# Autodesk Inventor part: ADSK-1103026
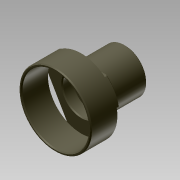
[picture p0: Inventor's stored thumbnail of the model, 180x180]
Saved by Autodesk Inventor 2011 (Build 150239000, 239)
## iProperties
Shininess: 41.0
Length Units: 11272
Angle Units: 11279
Time Units: 11290
Mass Units: 11286
Length Display Precision: 4
Angle Display Precision: 2
Compacted: True
Created: 2000-08
Part Number: ADSK-1103026
Document SubType Name: Modeling
Description: 24 TOOTH CLUTCH GEAR
Mass: 3.13134 g
Surface Area: 23.3651 cm^2
Volume: 1.15548 cm^3
Density: 2.71 g/cm^3
Material: Aluminum-6061
Density: 0.0
Volumn: 0.0
Area: 0.0
PropertySet Name: Model Information
Control State: 0
Master: False
Checked Out: False
Author: Autodesk, Inc.
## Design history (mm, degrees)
node "Extrusion1" dims "d1" = 8.4328, "d2" = 0
  sketch "Sketch3"
    geometry: C1 r 10.477 at (-1.128, -0.122)
    constraints: 1 centre point
    dimensions: "d0" = 20.955 diameter of C1
node "Shell1" dims "d3" = 0.8128
node "Extrusion2" dims "d5" = 11.8872, "d6" = 0
  sketch "Sketch4"
    geometry: C1 r 10.477 at (0, 0) reference; C2 r 6.35 at (0, 0)
    constraints: 1 centre point, 1 concentric
    dimensions: "d4" = 12.7 diameter of C2
node "Extrusion3" dims "d8" = 0.8128, "d9" = 0
  sketch "Sketch5"
    geometry: L1 (-6.839, 7.938)-(6.839, 7.938); A1 r 10.477 centre (0, 0) between (-6.839, 7.938) and (6.839, 7.938) reference
    constraints: 2 end point, 2 point on circle, 1 horizontal
    dimensions: "d7" = 2.54 distance edge to line of A1 L1
node "Circular Pattern1" dims "d10" = 30, "d12" = 360 deg
node "Extrusion4" dims "d14" = 2.99974, "d15" = 0
  sketch "Sketch6"
    geometry: C1 r 6.35 at (0, 0) reference; C2 r 5.524 at (0, 0)
    constraints: 1 centre point, 1 coincident
    dimensions: "d13" = 11.049 diameter of C2
node "Extrusion5" dims "d16" = 2.99974, "d17" = 0
  sketch "Sketch7"
    geometry: C1 r 5.524 at (5.514, -7.938) reference
node "Extrusion6" dims "d19" = 2.54, "d20" = 0
  sketch "Sketch8"
    geometry: C1 r 5.524 at (0, 0) reference; C2 r 4.255 at (0, 0)
    constraints: 1 centre point, 1 coincident
    dimensions: "d18" = 1.27 radial gap between concentric circles of C1 C2
node "Chamfer1" dims "d21" = 0.254, "d22" = 0.254, "d23" = 45 deg
body "Solid1"
